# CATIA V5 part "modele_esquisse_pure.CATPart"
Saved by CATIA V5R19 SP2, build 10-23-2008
Part number: Pièce1
Bounding box of the stored display mesh (mm): x 0 to 0, y -247.391 to 900, z -1978.599 to 0
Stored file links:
  C:\Users\matthieu\Desktop\IAO\modele_CAO\modele_esquisse_pure.CATPart
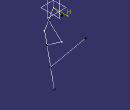
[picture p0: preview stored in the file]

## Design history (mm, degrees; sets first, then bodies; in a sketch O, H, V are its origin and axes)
Parameters
  a = 250 mm
  b = 400 mm
  c = 325 mm
  d = 500 mm
  e = 500 mm
  f = 500 mm
  h = 300 mm
  i = 900 mm
  g = 1540.2922 mm {= sqrt(((b +2*c+e -h  )/1mm)*((b +2*c+e -h )/1mm)+((i )/1mm)*((i )/1mm))*1mm}
Body1 (main body)
  Sketch1 on yz-plane, origin (0, 0, 0), H (0, 1, 0), V (0, 0, 1)
    line L1 (234.995, -85.3073) -> (0, 0)
    point P1 (234.995, -85.3073)
    line L2 (0, 0) -> (-136.4916, -375.9921)
    line L3 (-136.4916, -375.9921) -> (-247.3911, -681.4856)
    point P3 (-247.3911, -681.4856)
    line L4 (-136.4916, -375.9921) -> (230.4436, -715.6368)
    point P4 (230.4436, -715.6368)
    line L5 (230.4436, -715.6368) -> (-181.0646, -999.6456)
    point P5 (-181.0646, -999.6456)
    line L6 (-181.0646, -999.6456) -> (-247.3911, -681.4856)
    line L7 (-181.0646, -999.6456) -> (-79.0238, -1489.1226)
    point P6 (-79.0238, -1489.1226)
    line L8 (-79.0238, -1489.1226) -> (23.0171, -1978.5995)
    point P7 (23.0171, -1978.5995)
    line L9 (-79.0238, -1489.1226) -> (900, -300)
    point P8 (900, -300)
    length L2 = 400 {= b}
    length L1 = 250 {= a}
    length L3 = 325 {= c}
    distance P5 P3 = 325 {= c}
    distance P5 P6 = 500 {= e}
    length L8 = 500 {= f}
    length L9 = 1540.2922 {= g}
    distance P8 V = 900 {= i}
    distance P8 H = 300 {= h}
    length L5 = 500
    length L4 = 500
    distance P7 H = 1978.5995 (reference)
    distance P4 P1 = 630.3459 (reference)
    perpendicularity: L2 L1
    parallelism: L3 L2, L7 L6, L8 L7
